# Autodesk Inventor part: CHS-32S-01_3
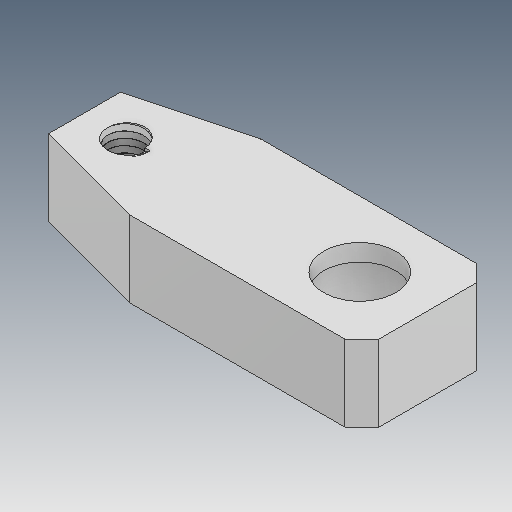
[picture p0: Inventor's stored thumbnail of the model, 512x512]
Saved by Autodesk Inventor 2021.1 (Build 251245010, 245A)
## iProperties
Created: 2021-05
Part Number: CHS-32S-01_3
Material: Ogólny
Document SubType Name: Modeling
Designer: user
Density: 1 g/cm^3
Appearance: Domyślna
Author: user
Revision Number: ÈÎºÎ
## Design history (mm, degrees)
feature "ÊäÈë1"
node "Bryła1"
